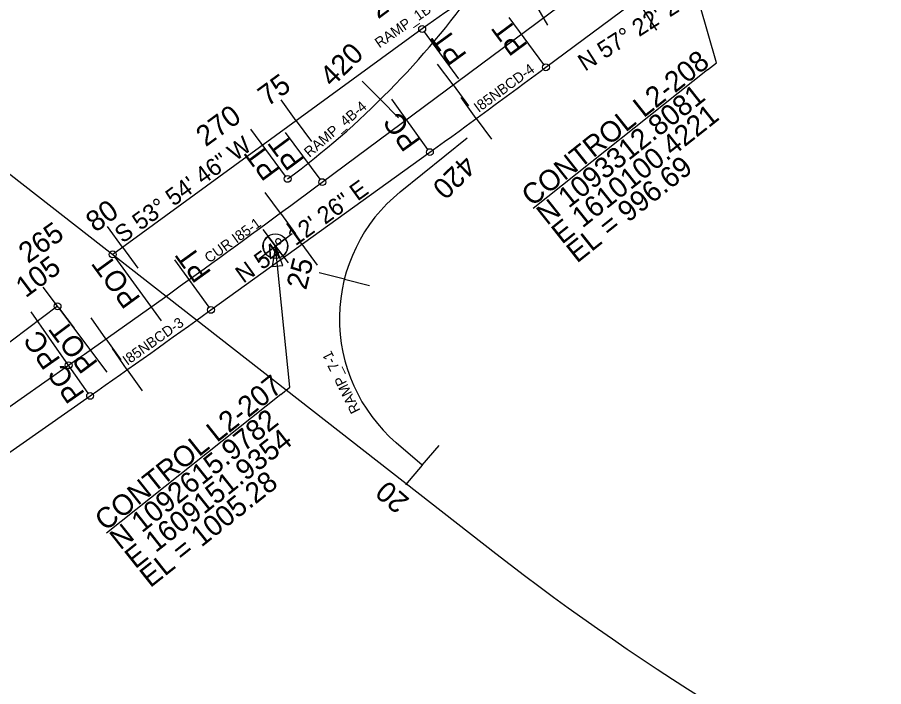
# Model space of a CAD drawing. Extents: x 1603447 to 1622636, y 1083818 to 1103958.
# Drawn here: x 1608552 to 1610566, y 1091591 to 1093148 of the extents above; entities that cross this region are included whole.
import ezdxf

# ---------------------------------------------------------------- set-up
doc = ezdxf.new("R2010")
doc.units = 0
for name, color, linetype in [('Level 1', 7, 'Continuous'), ('RD_HC_Points', 7, 'Continuous'), ('RD_HC_SUR_Bearing_TX400', 7, 'Continuous'), ('RD_HC_SUR_CL400', 7, 'Continuous'), ('RD_HC_SUR_PC_PT_400', 7, 'Continuous'), ('RD_HC_SUR_Tic400', 7, 'Continuous'), ('RD_HC_SUR_TX_Sta400', 7, 'Continuous'), ('RD_SHT_Misc1', 7, 'Continuous'), ('RD_TX_Misc1', 7, 'Continuous')]:
    doc.layers.add(name, color=color, linetype=linetype)

msp = doc.modelspace()

# ---------------------------------------------------------------- linework, layer by layer
at = {"layer": 'RD_HC_Points'}
for p, q in [((1610156.3, 1093025.9), (1609751.1, 1092703.6)), ((1609164.4, 1092271), (1608759, 1091948.5))]:
    msp.add_line(p, q, dxfattribs=at)
for points in [[(1610156.3, 1093025.9), (1610177.4, 1093042.6), (1610100.4, 1093312.8)], [(1609164.4, 1092271), (1609185.4, 1092287.7), (1609151.9, 1092616)]]:
    msp.add_lwpolyline(points, dxfattribs=at)
msp.add_lwpolyline([(1609169, 1092571.1), (1609151.9, 1092616), (1609144.3, 1092568.6)], close=True, dxfattribs=at)
at = {"layer": 'RD_HC_SUR_CL400'}
for p, q in [((1609261, 1092765), (1614429, 1096606.7)), ((1609780.9, 1093032.2), (1610899.7, 1093863.9)), ((1609493.2, 1093121.2), (1608773.6, 1092596.8)), ((1608227.5, 1093023.1), (1609664.5, 1091901.4)), ((1609442.3, 1092742.4), (1609598.2, 1092868.1)), ((1609002.2, 1092467.8), (1609511.1, 1092834.7)), ((1608645.4, 1092476.2), (1608031.1, 1092016.1)), ((1604403.9, 1089345.9), (1608671.2, 1092339.1)), ((1607863.8, 1091666.5), (1608721.2, 1092267.8)), ((1609493.4, 1092106.6), (1609433, 1092158.5))]:
    msp.add_line(p, q, dxfattribs=at)
for centre, radius, start, end in [((1610965.7, 1091100.9), 2500, 120.2008, 126.0872), ((1607990.9, 1094380.3), 2000, 306.4947, 324.5024), ((1596059.5, 1111490.8), 23000, 305.79282, 306.62559), ((1593508.4, 1113956.1), 26404.7, 305.04683, 306.62559), ((1609680.9, 1092446.6), 380, 128.8796, 229.2983), ((1593508.4, 1113956.1), 26491.6, 305.04683, 305.79282), ((1613190, 1096417.9), 5729.6, 232.02562, 245.46665)]:
    msp.add_arc(centre, radius, start, end, dxfattribs=at)
at = {"layer": 'RD_HC_SUR_PC_PT_400'}
for p, q in [((1609712.2, 1093254.7), (1609784.5, 1093130.4)), ((1609776.1, 1093038.6), (1609695.1, 1093147.6)), ((1609497.9, 1093114.8), (1609577.9, 1093005)), ((1609506.5, 1092841.2), (1609422.4, 1092957.8)), ((1609175.7, 1092778.9), (1609094.9, 1092888.1)), ((1609256.2, 1092771.5), (1609175.2, 1092880.5)), ((1608778.3, 1092590.3), (1608886.4, 1092442.1)), ((1608997.6, 1092474.2), (1608918.1, 1092584.4)), ((1608666.6, 1092345.6), (1608584, 1092463.3)), ((1608650.2, 1092469.8), (1608760.1, 1092323)), ((1608716.6, 1092274.4), (1608634, 1092392.1))]:
    msp.add_line(p, q, dxfattribs=at)
for centre in [(1609493.2, 1093121.2), (1609780.9, 1093032.2), (1609511.1, 1092834.7), (1609180.4, 1092772.5), (1609261, 1092765), (1608773.6, 1092596.8), (1608645.4, 1092476.2), (1609002.2, 1092467.8), (1608671.2, 1092339.1), (1608721.2, 1092267.8)]:
    msp.add_circle(centre, 8, dxfattribs=at)
at = {"layer": 'RD_HC_SUR_Tic400'}
for p, q in [((1610005.3, 1093169.1), (1610037.7, 1093118.6)), ((1609524, 1093143.3), (1609524, 1093143.3)), ((1609531.2, 1093104.5), (1609531.2, 1093104.5)), ((1609725.4, 1093110.2), (1609725.4, 1093110.2)), ((1609443, 1093084.7), (1609443, 1093084.7)), ((1609860.4, 1093091.3), (1609860.4, 1093091.3)), ((1609564.9, 1092990.9), (1609529.1, 1093039.1)), ((1609645.2, 1093050.6), (1609645.2, 1093050.6)), ((1609362.2, 1093025.7), (1609362.2, 1093025.7)), ((1609465.5, 1093029.2), (1609465.5, 1093029.2)), ((1609780.2, 1093031.6), (1609780.2, 1093031.6)), ((1609396.1, 1092957.1), (1609354, 1092999.8)), ((1609564.9, 1092990.9), (1609600.7, 1092942.8)), ((1609200.6, 1092907.9), (1609165.2, 1092956.4)), ((1609281.4, 1092966.8), (1609281.4, 1092966.8)), ((1609396.1, 1092957.1), (1609438.3, 1092914.5)), ((1609619.1, 1092913), (1609583.8, 1092961.5)), ((1609699.8, 1092972.2), (1609699.8, 1092972.2)), ((1609484.7, 1092931.3), (1609484.7, 1092931.3)), ((1609200.6, 1092907.9), (1609235.9, 1092859.5)), ((1609619.1, 1092913), (1609654.5, 1092864.6)), ((1609323.2, 1092888.7), (1609323.2, 1092888.7)), ((1609538.2, 1092854.2), (1609538.2, 1092854.2)), ((1609119.8, 1092849), (1609119.8, 1092849)), ((1609562.6, 1092839.3), (1609562.6, 1092839.3)), ((1609247, 1092824), (1609247, 1092824)), ((1609457.1, 1092795.7), (1609457.1, 1092795.7)), ((1609039, 1092790.1), (1609039, 1092790.1)), ((1609484.7, 1092776.6), (1609484.7, 1092776.6)), ((1609163.5, 1092692.9), (1609127.9, 1092741.2)), ((1609376, 1092737.3), (1609376, 1092737.3)), ((1608958.1, 1092731.2), (1608958.1, 1092731.2)), ((1609163.5, 1092692.9), (1609199, 1092644.5)), ((1609408.7, 1092711.8), (1609408.7, 1092711.8)), ((1608877.3, 1092672.3), (1608877.3, 1092672.3)), ((1609294.9, 1092678.8), (1609294.9, 1092678.8)), ((1608796.5, 1092613.4), (1608761.2, 1092661.9)), ((1609213.8, 1092620.3), (1609178.7, 1092669)), ((1609082.8, 1092633.7), (1609082.8, 1092633.7)), ((1608796.5, 1092613.4), (1608831.9, 1092565)), ((1609213.8, 1092620.3), (1609248.9, 1092571.6)), ((1609349.1, 1092631.8), (1609349.1, 1092631.8)), ((1609002, 1092574.9), (1609002, 1092574.9)), ((1609132.7, 1092561.8), (1609132.7, 1092561.8)), ((1609312.3, 1092539.1), (1609254.1, 1092553.7)), ((1609312.3, 1092539.1), (1609370.5, 1092524.5)), ((1608647.8, 1092473), (1608611.9, 1092521)), ((1608920.9, 1092516.4), (1608920.9, 1092516.4)), ((1609051.6, 1092503.3), (1609051.6, 1092503.3)), ((1608647.8, 1092473), (1608683.8, 1092425)), ((1608839.6, 1092458.2), (1608839.6, 1092458.2)), ((1608758, 1092400.2), (1608723.4, 1092449.2)), ((1608970.4, 1092444.9), (1608970.4, 1092444.9)), ((1609300.9, 1092440.1), (1609300.9, 1092440.1)), ((1608567.8, 1092413.1), (1608567.8, 1092413.1)), ((1608758, 1092400.2), (1608792.7, 1092351.3)), ((1608807.6, 1092328.7), (1608772.9, 1092377.7)), ((1608889.1, 1092386.6), (1608889.1, 1092386.6)), ((1608676.3, 1092342.7), (1608676.3, 1092342.7)), ((1609315.7, 1092341.5), (1609315.7, 1092341.5)), ((1608807.6, 1092328.7), (1608842.2, 1092279.8)), ((1608594.4, 1092285.2), (1608594.4, 1092285.2)), ((1608725.8, 1092271.1), (1608725.8, 1092271.1)), ((1609355.6, 1092250.1), (1609355.6, 1092250.1)), ((1608644, 1092213.7), (1608644, 1092213.7)), ((1609417.9, 1092172.2), (1609417.9, 1092172.2)), ((1608562.1, 1092156.3), (1608562.1, 1092156.3)), ((1609493.4, 1092106.6), (1609532.5, 1092152.1)), ((1609493.4, 1092106.6), (1609454.2, 1092061.1))]:
    msp.add_line(p, q, dxfattribs=at)
at = {"layer": 'RD_SHT_Misc1'}
for p, q in [((1609122.4, 1092654.8), (1609181.4, 1092577.2)), ((1609113.1, 1092586.5), (1609190.7, 1092645.5)), ((1609151.9, 1092616), (1609134.5, 1092638.9)), ((1609174.8, 1092633.4), (1609151.9, 1092616)), ((1609129, 1092598.6), (1609151.9, 1092616)), ((1609151.9, 1092616), (1609169.3, 1092593.1))]:
    msp.add_line(p, q, dxfattribs=at)
msp.add_circle((1609151.9, 1092616), 28.8, dxfattribs=at)
for start, end in [(127.2464, 217.2464), (307.2464, 37.2464)]:
    msp.add_arc((1609151.9, 1092616), 28.8, start, end, dxfattribs=at)

# ---------------------------------------------------------------- texts
at = {"layer": 'Level 1'}
for s, rotation, p in [('275', 36.6256, (1609390.9, 1093143.2)), ('75', 36.0872, (1609133.9, 1092939.5)), ('265', 35.2773, (1608576.7, 1092574.5)), ('105', 36.8151, (1608571.3, 1092494.4)), ('25', 75.9046, (1609223.3, 1092512.5))]:
    msp.add_text(s, height=48, rotation=rotation, dxfattribs=at).set_placement(p)
at = {"layer": 'RD_HC_Points'}
for s, p in [('CONTROL L2-208', (1609748.6, 1092706.7)), ('N 1093312.8081', (1609783.5, 1092662.9)), ('E 1610100.4221', (1609818.3, 1092619)), ('EL = 996.69', (1609853.2, 1092575.2)), ('CONTROL L2-207', (1608756.5, 1091951.6)), ('N 1092615.9782', (1608791.3, 1091907.8)), ('E 1609151.9354', (1608826.2, 1091864)), ('EL = 1005.28', (1608861, 1091820.2))]:
    msp.add_text(s, height=48, rotation=38.4995, dxfattribs=at).set_placement(p)
at = {"layer": 'RD_HC_SUR_Bearing_TX400'}
for s, rotation, p in [('N 57%%d 22\' 28" E', 32.6256, (1609871.9, 1093021.6)), ('S 53%%d 54\' 46" W', 36.0872, (1608796.9, 1092621.4)), ('N 54%%d 12\' 26" E', 35.7928, (1609077.6, 1092528.3))]:
    msp.add_text(s, height=40, rotation=rotation, dxfattribs=at).set_placement(p)
at = {"layer": 'RD_HC_SUR_PC_PT_400'}
for s, rotation, p in [('PT', 126.6256, (1609740.5, 1093083.1)), ('PT', 126.0872, (1609598.8, 1093060.8)), ('PC', 125.7928, (1609490.5, 1092859.7)), ('PT', 126.6256, (1609220.6, 1092816)), ('PT', 126.4947, (1609165, 1092792.4)), ('PT', 125.7928, (1609004.5, 1092554.6)), ('POT', 126.0872, (1608840.1, 1092494.5)), ('POT', 126.8151, (1608740.9, 1092343.8)), ('PC', 125.0468, (1608653.9, 1092351.7)), ('PC', 125.0468, (1608710.2, 1092272.9))]:
    msp.add_text(s, height=48, rotation=rotation, dxfattribs=at).set_placement(p)
at = {"layer": 'RD_HC_SUR_TX_Sta400'}
for s, rotation, p in [('420', 44.6355, (1609284.1, 1092984.1)), ('270', 36.3623, (1608990, 1092845.8)), ('420', 224.6355, (1609589.8, 1092830.8)), ('80', 36.0872, (1608733.6, 1092646.6)), ('20', 139.2983, (1609466, 1092027))]:
    msp.add_text(s, height=48, rotation=rotation, dxfattribs=at).set_placement(p)
at = {"layer": 'RD_TX_Misc1'}
for s, rotation, p in [('RAMP_1B-2', 34.9418, (1609393.7, 1093075.8)), ('I85NBCD-4', 36.2462, (1609624.5, 1092925.9)), ('RAMP_4B-4', 40.6416, (1609231.2, 1092821.2)), ('CUR I85-1', 35.8362, (1608998.1, 1092575.6)), ('I85NBCD-3', 35.3971, (1608807.5, 1092337.7)), ('RAMP_7-1', 116.1431, (1609350.3, 1092233.9))]:
    msp.add_text(s, height=24, rotation=rotation, dxfattribs=at).set_placement(p)

doc.saveas('drawing.dxf')
